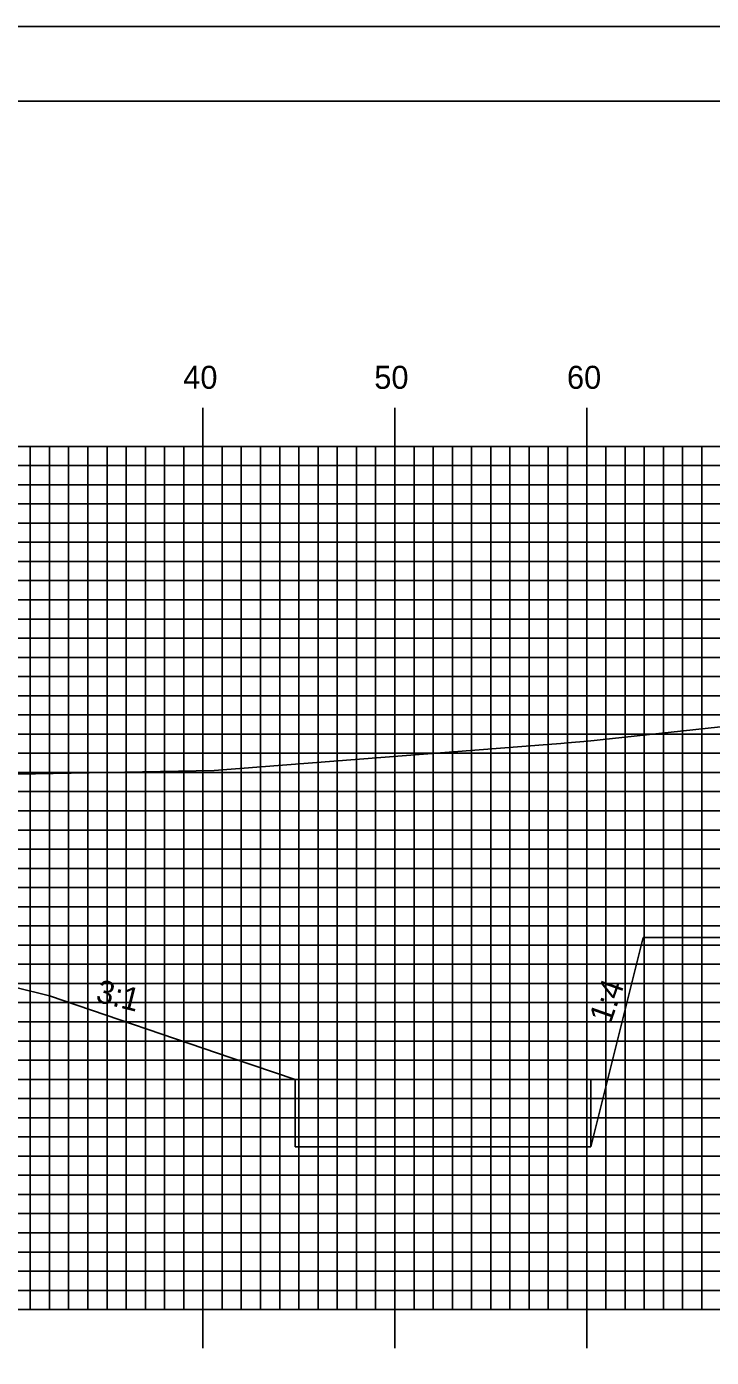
# Model space of a CAD drawing. Extents: x 1793666 to 1794009, y 442591 to 442811.
# Drawn here: x 1793862.1 to 1793897.8, y 442741.2 to 442810.5 of the extents above; entities that cross this region are included whole.
import ezdxf

# ---------------------------------------------------------------- set-up
doc = ezdxf.new("R2010")
doc.units = 0
for name, color, linetype in [('ANNOTATION', 7, 'Continuous'), ('BORDER', 7, 'Continuous'), ('D_Roadway_FinishedGrade', 7, 'Continuous'), ('D_Roadway_SlopeLines', 7, 'Continuous'), ('D_Roadway_SubGrade', 7, 'Continuous'), ('H_V ANNOTATION', 7, 'Continuous'), ('MAJOR', 7, 'Continuous'), ('MINOR', 7, 'Continuous'), ('PLOT BOUNDARY', 7, 'Continuous'), ('S_Roadway_Centerline', 7, 'Continuous')]:
    doc.layers.add(name, color=color, linetype=linetype)

msp = doc.modelspace()

# ---------------------------------------------------------------- linework, layer by layer
at = {"layer": 'BORDER'}
msp.add_lwpolyline([(1793681.714, 442596.665), (1794001.714, 442596.665), (1794001.714, 442806.665), (1793681.714, 442806.665)], close=True, dxfattribs=at)
at = {"layer": 'D_Roadway_FinishedGrade'}
for p, q in [((1793876.125, 442755.651), (1793891.537, 442755.651)), ((1793891.537, 442755.651), (1793891.537, 442752.15))]:
    msp.add_line(p, q, dxfattribs=at)
for points in [[(1793876.126, 442755.65), (1793891.537, 442755.651)], [(1793891.537, 442755.651), (1793891.537, 442752.651)], [(1793876.126, 442752.15), (1793891.537, 442752.15)]]:
    msp.add_lwpolyline(points, dxfattribs=at)
at = {"layer": 'D_Roadway_SlopeLines'}
for p, q in [((1793891.537, 442752.15), (1793894.266, 442763.065)), ((1793894.266, 442763.065), (1793900.266, 442763.065))]:
    msp.add_line(p, q, dxfattribs=at)
at = {"layer": 'D_Roadway_SubGrade'}
msp.add_line((1793861.488, 442760.479), (1793863.314, 442760.022), dxfattribs=at)
msp.add_lwpolyline([(1793863.314, 442760.022), (1793872.785, 442756.79), (1793876.126, 442755.65), (1793876.126, 442752.15)], dxfattribs=at)
at = {"layer": 'MAJOR'}
for p, q in [((1793871.314, 442790.669), (1793871.314, 442788.665)), ((1793881.314, 442790.669), (1793881.314, 442788.665)), ((1793891.314, 442790.669), (1793891.314, 442788.665)), ((1793691.314, 442788.665), (1793971.314, 442788.665)), ((1793691.314, 442788.665), (1793971.314, 442788.665)), ((1793871.314, 442743.665), (1793871.314, 442788.665)), ((1793881.314, 442743.665), (1793881.314, 442788.665)), ((1793891.314, 442743.665), (1793891.314, 442788.665)), ((1793691.314, 442783.665), (1793971.314, 442783.665)), ((1793691.314, 442778.665), (1793971.314, 442778.665)), ((1793691.314, 442773.665), (1793971.314, 442773.665)), ((1793691.314, 442768.665), (1793971.314, 442768.665)), ((1793691.314, 442763.665), (1793971.314, 442763.665)), ((1793691.314, 442758.665), (1793971.314, 442758.665)), ((1793691.314, 442753.665), (1793971.314, 442753.665)), ((1793691.314, 442748.665), (1793971.314, 442748.665)), ((1793691.314, 442743.665), (1793971.314, 442743.665)), ((1793691.314, 442743.665), (1793971.314, 442743.665)), ((1793871.314, 442741.661), (1793871.314, 442743.665)), ((1793881.314, 442741.661), (1793881.314, 442743.665)), ((1793891.314, 442741.661), (1793891.314, 442743.665))]:
    msp.add_line(p, q, dxfattribs=at)
at = {"layer": 'MINOR'}
for p, q in [((1793862.314, 442743.665), (1793862.314, 442788.665)), ((1793863.314, 442743.665), (1793863.314, 442788.665)), ((1793864.314, 442743.665), (1793864.314, 442788.665)), ((1793865.314, 442743.665), (1793865.314, 442788.665)), ((1793866.314, 442743.665), (1793866.314, 442788.665)), ((1793867.314, 442743.665), (1793867.314, 442788.665)), ((1793868.314, 442743.665), (1793868.314, 442788.665)), ((1793869.314, 442743.665), (1793869.314, 442788.665)), ((1793870.314, 442743.665), (1793870.314, 442788.665)), ((1793872.314, 442743.665), (1793872.314, 442788.665)), ((1793873.314, 442743.665), (1793873.314, 442788.665)), ((1793874.314, 442743.665), (1793874.314, 442788.665)), ((1793875.314, 442743.665), (1793875.314, 442788.665)), ((1793876.314, 442743.665), (1793876.314, 442788.665)), ((1793877.314, 442743.665), (1793877.314, 442788.665)), ((1793878.314, 442743.665), (1793878.314, 442788.665)), ((1793879.314, 442743.665), (1793879.314, 442788.665)), ((1793880.314, 442743.665), (1793880.314, 442788.665)), ((1793882.314, 442743.665), (1793882.314, 442788.665)), ((1793883.314, 442743.665), (1793883.314, 442788.665)), ((1793884.314, 442743.665), (1793884.314, 442788.665)), ((1793885.314, 442743.665), (1793885.314, 442788.665)), ((1793886.314, 442743.665), (1793886.314, 442788.665)), ((1793887.314, 442743.665), (1793887.314, 442788.665)), ((1793888.314, 442743.665), (1793888.314, 442788.665)), ((1793889.314, 442743.665), (1793889.314, 442788.665)), ((1793890.314, 442743.665), (1793890.314, 442788.665)), ((1793892.314, 442743.665), (1793892.314, 442788.665)), ((1793893.314, 442743.665), (1793893.314, 442788.665)), ((1793894.314, 442743.665), (1793894.314, 442788.665)), ((1793895.314, 442743.665), (1793895.314, 442788.665)), ((1793896.314, 442743.665), (1793896.314, 442788.665)), ((1793897.314, 442743.665), (1793897.314, 442788.665)), ((1793691.314, 442787.665), (1793971.314, 442787.665)), ((1793691.314, 442786.665), (1793971.314, 442786.665)), ((1793691.314, 442785.665), (1793971.314, 442785.665)), ((1793691.314, 442784.665), (1793971.314, 442784.665)), ((1793691.314, 442782.665), (1793971.314, 442782.665)), ((1793691.314, 442781.665), (1793971.314, 442781.665)), ((1793691.314, 442780.665), (1793971.314, 442780.665)), ((1793691.314, 442779.665), (1793971.314, 442779.665)), ((1793691.314, 442777.665), (1793971.314, 442777.665)), ((1793691.314, 442776.665), (1793971.314, 442776.665)), ((1793691.314, 442775.665), (1793971.314, 442775.665)), ((1793691.314, 442774.665), (1793971.314, 442774.665)), ((1793691.314, 442772.665), (1793971.314, 442772.665)), ((1793691.314, 442771.665), (1793971.314, 442771.665)), ((1793691.314, 442770.665), (1793971.314, 442770.665)), ((1793691.314, 442769.665), (1793971.314, 442769.665)), ((1793691.314, 442767.665), (1793971.314, 442767.665)), ((1793691.314, 442766.665), (1793971.314, 442766.665)), ((1793691.314, 442765.665), (1793971.314, 442765.665)), ((1793691.314, 442764.665), (1793971.314, 442764.665)), ((1793691.314, 442762.665), (1793971.314, 442762.665)), ((1793691.314, 442761.665), (1793971.314, 442761.665)), ((1793691.314, 442760.665), (1793971.314, 442760.665)), ((1793691.314, 442759.665), (1793971.314, 442759.665)), ((1793691.314, 442757.665), (1793971.314, 442757.665)), ((1793691.314, 442756.665), (1793971.314, 442756.665)), ((1793691.314, 442755.665), (1793971.314, 442755.665)), ((1793691.314, 442754.665), (1793971.314, 442754.665)), ((1793691.314, 442752.665), (1793971.314, 442752.665)), ((1793691.314, 442751.665), (1793971.314, 442751.665)), ((1793691.314, 442750.665), (1793971.314, 442750.665)), ((1793691.314, 442749.665), (1793971.314, 442749.665)), ((1793691.314, 442747.665), (1793971.314, 442747.665)), ((1793691.314, 442746.665), (1793971.314, 442746.665)), ((1793691.314, 442745.665), (1793971.314, 442745.665)), ((1793691.314, 442744.665), (1793971.314, 442744.665))]:
    msp.add_line(p, q, dxfattribs=at)
at = {"layer": 'PLOT BOUNDARY'}
msp.add_lwpolyline([(1793665.527, 442590.547), (1794005.527, 442590.547), (1794005.527, 442810.547), (1793665.527, 442810.547)], close=True, dxfattribs=at)
at = {"layer": 'S_Roadway_Centerline'}
msp.add_lwpolyline([(1793854.181, 442771.431), (1793871.898, 442771.772), (1793889.266, 442773.116), (1793889.964, 442773.178), (1793890.315, 442773.208), (1793891.369, 442773.301), (1793908.749, 442775.18), (1793913.388, 442775.967), (1793915.64, 442776.268), (1793921.201, 442776.988), (1793925.957, 442778.478), (1793926.388, 442778.609), (1793926.662, 442778.697), (1793939.509, 442778.53)], dxfattribs=at)

# ---------------------------------------------------------------- texts
at = {"layer": 'ANNOTATION'}
for s, rotation, p in [('3:1', 345.96376, (1793865.673, 442759.728)), ('1:4', 70.51601, (1793892.546, 442758.495)), ('1:4', 70.51601, (1793892.546, 442758.495))]:
    msp.add_text(s, height=1.2, rotation=rotation, dxfattribs=at).set_placement(p)
at = {"layer": 'H_V ANNOTATION'}
for s, p in [('40', (1793870.286, 442791.665)), ('50', (1793880.243, 442791.665)), ('60', (1793890.286, 442791.665))]:
    msp.add_text(s, height=1.2, dxfattribs=at).set_placement(p)

doc.saveas('drawing.dxf')
